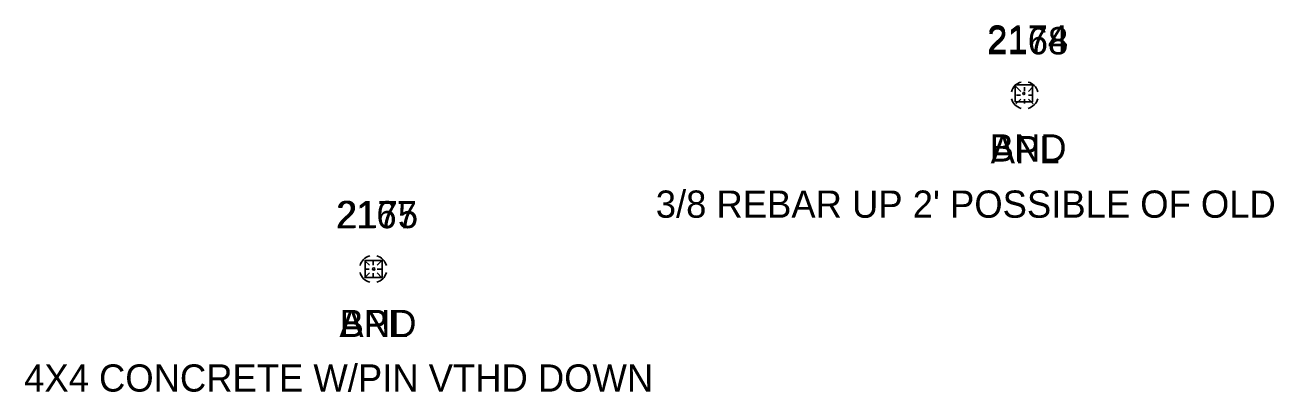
# Model space of a CAD drawing. Extents: x 1600395 to 1603269, y 874955 to 877143.
# Drawn here: x 1600815.1 to 1600906.9, y 875765.3 to 875792.2 of the extents above; entities that cross this region are included whole.
import ezdxf

# ---------------------------------------------------------------- set-up
doc = ezdxf.new("R2010")
doc.units = 0
for name, color, linetype in [('M_A', 7, 'Continuous'), ('M_C', 7, 'Continuous'), ('M_I', 7, 'Continuous'), ('MHBP', 7, 'Continuous'), ('MMP', 7, 'Continuous')]:
    doc.layers.add(name, color=color, linetype=linetype)

msp = doc.modelspace()

# ---------------------------------------------------------------- linework, layer by layer
at = {"layer": 'MHBP'}
for points in [[(1600887.89, 875787.811), (1600889.14, 875787.811), (1600889.14, 875786.561), (1600887.89, 875786.561)], [(1600840.134, 875774.92), (1600841.384, 875774.92), (1600841.384, 875773.67), (1600840.134, 875773.67)]]:
    msp.add_lwpolyline(points, close=True, dxfattribs=at)
for centre in [(1600888.515, 875787.186), (1600840.759, 875774.295)]:
    msp.add_circle(centre, 0.0833, dxfattribs=at)
at = {"layer": 'MMP'}
for p, q in [((1600887.934, 875787.695), (1600888.288, 875787.342)), ((1600888.57, 875787.359), (1600888.57, 875787.659)), ((1600888.853, 875787.342), (1600889.207, 875787.695)), ((1600887.934, 875786.423), (1600888.288, 875786.776)), ((1600887.97, 875787.059), (1600888.27, 875787.059)), ((1600888.57, 875786.459), (1600888.57, 875786.759)), ((1600888.853, 875786.776), (1600889.207, 875786.423)), ((1600888.87, 875787.059), (1600889.17, 875787.059)), ((1600840.082, 875774.924), (1600840.435, 875774.571)), ((1600840.718, 875774.588), (1600840.718, 875774.888)), ((1600841.001, 875774.571), (1600841.355, 875774.924)), ((1600840.082, 875773.651), (1600840.435, 875774.005)), ((1600840.118, 875774.288), (1600840.418, 875774.288)), ((1600840.718, 875773.688), (1600840.718, 875773.988)), ((1600841.001, 875774.005), (1600841.355, 875773.651)), ((1600841.018, 875774.288), (1600841.318, 875774.288))]:
    msp.add_line(p, q, dxfattribs=at)
for centre, start, end in [((1600888.57, 875787.059), 105, 165), ((1600888.57, 875787.059), 15, 75), ((1600888.57, 875787.059), 195, 255), ((1600888.57, 875787.059), 285, 345), ((1600840.718, 875774.288), 105, 165), ((1600840.718, 875774.288), 15, 75), ((1600840.718, 875774.288), 195, 255), ((1600840.718, 875774.288), 285, 345)]:
    msp.add_arc(centre, 1, start, end, dxfattribs=at)

# ---------------------------------------------------------------- texts
at = {"layer": 'M_A'}
for s, p in [('APL', (1600886.082, 875782.059)), ('BND', (1600886.004, 875782.186)), ('APL', (1600838.23, 875769.288)), ('BND', (1600838.248, 875769.295))]:
    msp.add_text(s, height=2, dxfattribs=at).set_placement(p)
at = {"layer": 'M_C'}
for s, p in [("3/8 REBAR UP 2' POSSIBLE OF OLD", (1600861.477, 875778.059)), ('4X4 CONCRETE W/PIN VTHD DOWN', (1600815.073, 875765.288))]:
    msp.add_text(s, height=2, dxfattribs=at).set_placement(p)
at = {"layer": 'M_I'}
for s, p in [('2174', (1600885.823, 875790.186)), ('2168', (1600885.83, 875790.059)), ('2167', (1600837.978, 875777.288)), ('2175', (1600838.067, 875777.295))]:
    msp.add_text(s, height=2, dxfattribs=at).set_placement(p)

doc.saveas('drawing.dxf')
